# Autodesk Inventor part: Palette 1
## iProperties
Shininess: 64.0
Length Units: 11269
Angle Units: 11279
Time Units: 11290
Mass Units: 11283
Length Display Precision: 3
Angle Display Precision: 2
Compacted: True
Part Number: Palette 1
Document SubType Name: Modeling
Created: 2005-01
Material: Par défaut
Designer: Flavien MARTY
Density: 0.0
Volumn: 0.0
Area: 0.0
PropertySet Name: Model Information
Control State: 0
Master: False
Checked Out: False
Norme de conversion: STEP AP203
Nom du fichier: Palette 1.STEP
Préprocesseur: SolidWorks 2001039
Postprocesseur: Build: Release: 6 RTM Build: 90b - Date: Tue 09/24/2002
Unités envoyées: MILLIMETERS
Incertitude: 0.0
Author: Flavien MARTY
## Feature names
1. Base1
